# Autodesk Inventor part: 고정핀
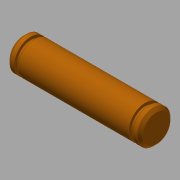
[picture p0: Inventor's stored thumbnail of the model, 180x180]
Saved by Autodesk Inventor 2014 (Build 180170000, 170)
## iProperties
Created: 2015-12
Part Number: 고정핀
Material: 스테인리스강
Document SubType Name: Modeling
Designer: mduedu
Density: 8.08 g/cm^3
Appearance: Orange
Author: mduedu
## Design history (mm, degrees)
sketch "스케치1"
  geometry: C1 r 3 at (0, 0); 1 further point
  constraints: 1 centre point, 1 coincident
  dimensions: "d0" = 6 diameter of C1
extrude "돌출1" new body sketch "스케치1" stored distance "d1" = 24; taper "d2" = 0 deg
chamfer "모따기1" distance "d3" = 0.5; stored, may be unused: second distance "d4" = 2, angle "d5" = 45 deg
sketch "스케치2"
  geometry: L1 (-12, 2.5)-(-11.5, 3) reference; L2 (-11.5, 3)-(11.5, 3) reference; L3 (11.5, 3)-(12, 2.5) reference; L4 (12, 2.5)-(12, -2.5) reference; L5 (12, -2.5)-(11.5, -3) reference; L6 (11.5, -3)-(-11.5, -3) reference; L7 (-11.5, -3)-(-12, -2.5) reference; L8 (-12, -2.5)-(-12, 2.5) reference; L9 (10, 3)-(10.7, 3); L10 (10.7, 3)-(10.7, 2.5); L11 (10.7, 2.5)-(10, 2.5); L12 (10, 2.5)-(10, 3); L13 (0, 0)-(12, 0)
  constraints: 10 end point, 2 parallel, 1 collinear, 1 horizontal, 1 midpoint, 1 perpendicular
  dimensions: "d6" = 10 distance from line of L12 L13.start; "d7" = 5 diameter of L11 L13; "d8" = 0.7 distance of L9.start L9.end
revolve "회전1" sketch "스케치2" stored, may be unused: angle "d9" = 90 deg
node "솔리드1"
mirror "대칭1"
node "절단 모서리 투영1"
